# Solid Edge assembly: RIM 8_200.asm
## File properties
Title: Zylinder
Author: psaghy
Template: iso metric assembly.asm
Last saved by: psaghy
Revision: 20
Application: Solid Edge
Username: psaghy
Dokumentum tartalom típus: 1
Document Number: RIM 8/200
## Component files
Kit_2.par
Kolbenstange.par
Profilrohr.par
Kit_1.par
Mutter_1.par
Mutter_2.par
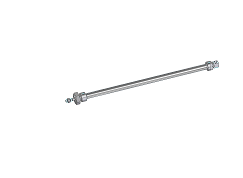
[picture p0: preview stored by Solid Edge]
